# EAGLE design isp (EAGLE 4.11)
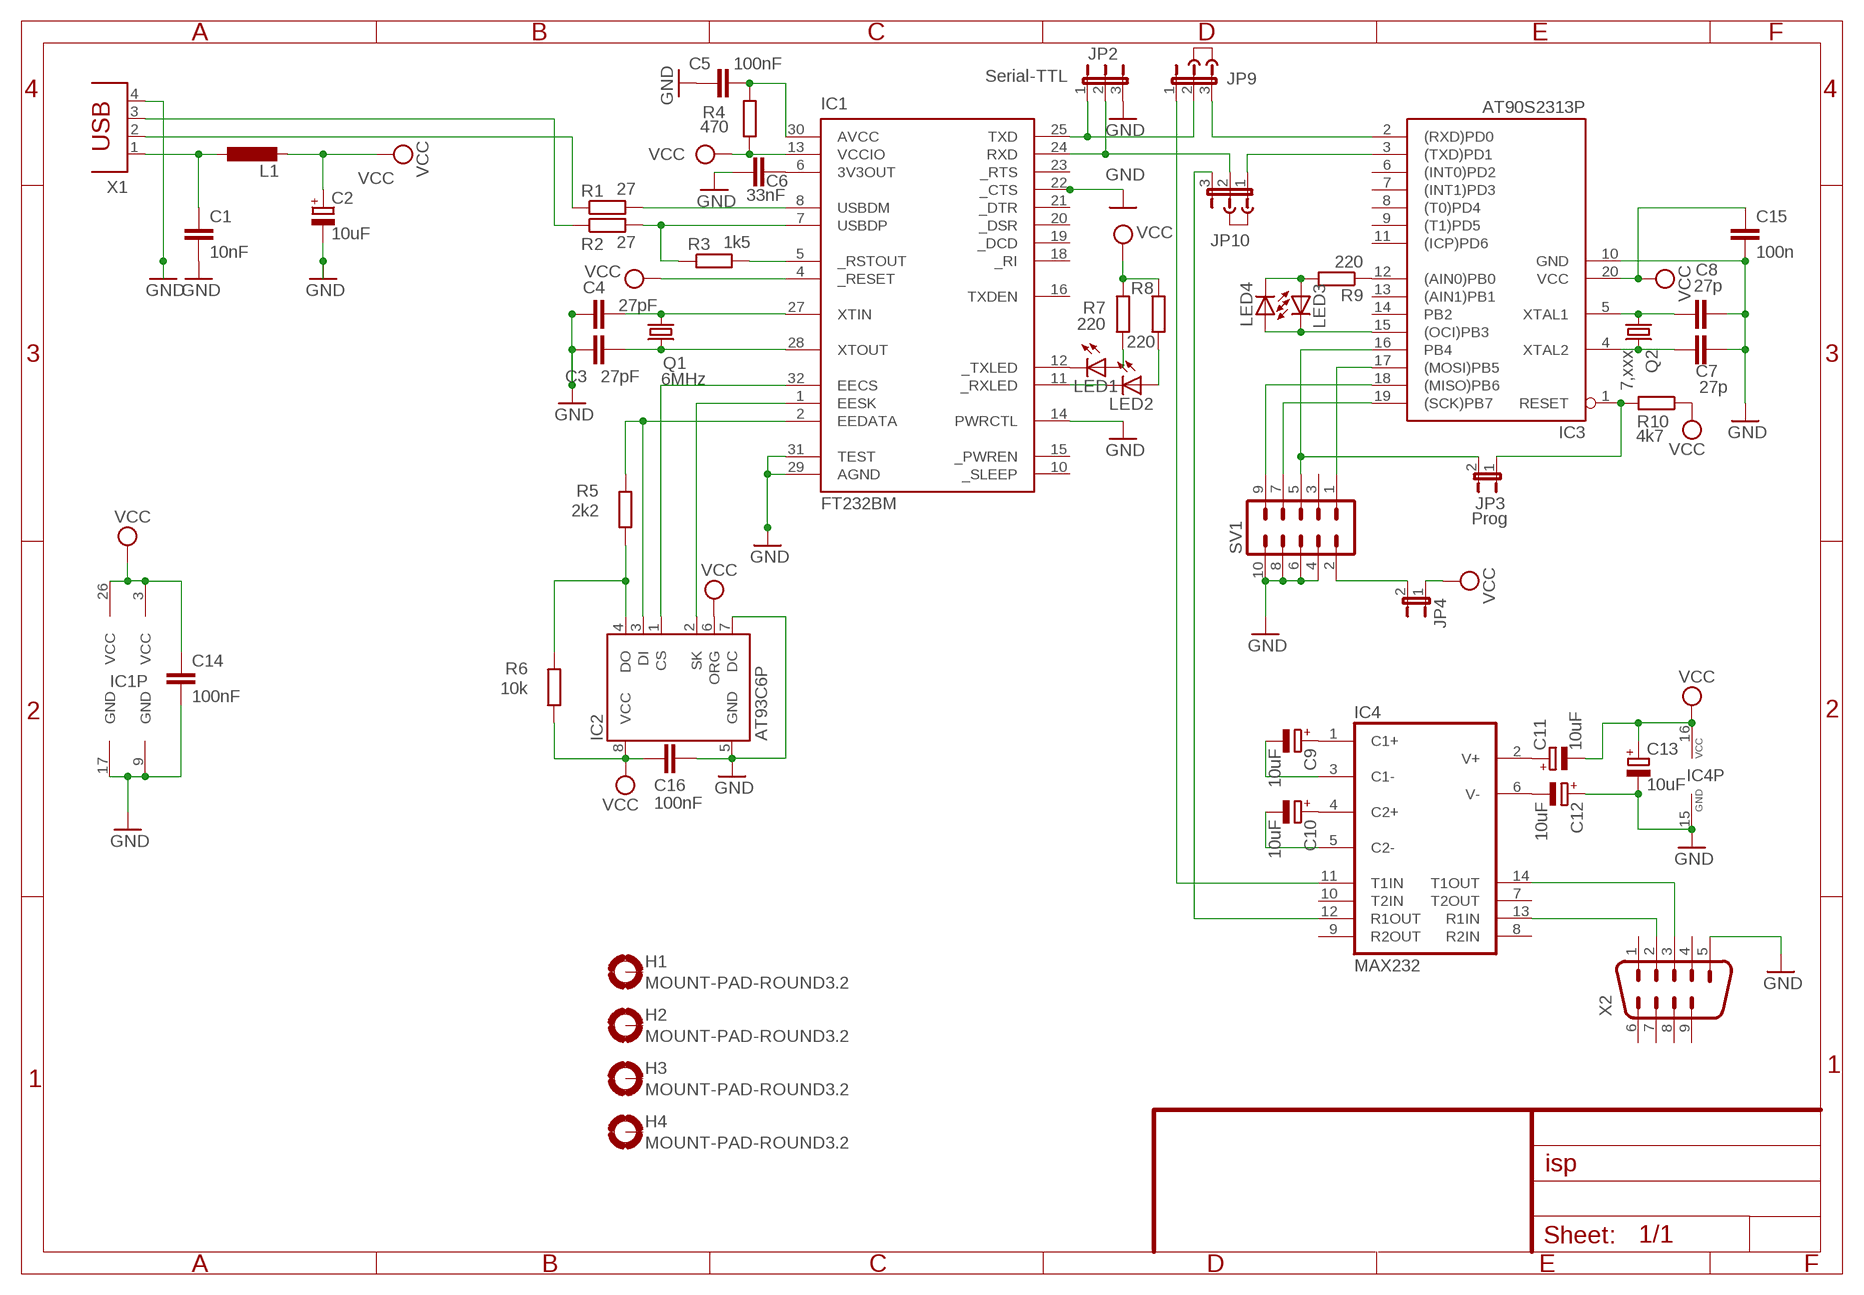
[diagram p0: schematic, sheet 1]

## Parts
C1  10nF  C-EU050-024X044  [C050-024X044]
C2  10uF  CPOL-EUE5-8.5  [E5-8,5]
C3  27pF  C-EU025-024X044  [C025-024X044]
C4  27pF  C-EU025-024X044  [C025-024X044]
C5  100nF  C-EU025-024X044  [C025-024X044]
C6  33nF  C-EU050-024X044  [C050-024X044]
C7  27p  C-EU025-024X044  [C025-024X044]
C8  27p  C-EU025-024X044  [C025-024X044]
C9  10uF  CPOL-EUE2.5-7  [E2,5-7]
C10  10uF  CPOL-EUE2.5-7  [E2,5-7]
C11  10uF  CPOL-EUE2.5-7  [E2,5-7]
C12  10uF  CPOL-EUE2.5-7  [E2,5-7]
C13  10uF  CPOL-EUE2.5-7  [E2,5-7]
C14  100nF  C-EU050-024X044  [C050-024X044]
C15  100n  C-EU050-024X044  [C050-024X044]
C16  100nF  C-EU050-024X044  [C050-024X044]
H1  MOUNT-PAD-ROUND3.2  [3,2-PAD]
H2  MOUNT-PAD-ROUND3.2  [3,2-PAD]
H3  MOUNT-PAD-ROUND3.2  [3,2-PAD]
H4  MOUNT-PAD-ROUND3.2  [3,2-PAD]
IC1  FT232BM  [LQFP32]
IC2  AT93C6P  [DIL08]
IC3  AT90S2313P  [DIL20]
IC4  MAX232  [DIL16]
J1  JUMPER  [JUMP]
J2  JUMPER  [JUMP]
JP2  Serial-TTL  JP2E  [JP2]
JP3  Prog  JP1E  [JP1]
JP4  JP1E  [JP1]
JP9  JP2E  [JP2]
JP10  JP2E  [JP2]
L1  L-EU0207/10  [0207/10]
LED1  LED3MM  [LED3MM]
LED2  LED3MM  [LED3MM]
LED3  LED3MM  [LED3MM]
LED4  LED3MM  [LED3MM]
Q1  6MHz  CRYTALHC49U-V  [HC49U-V]
Q2  7,xxx  CRYTALHC49U-V  [HC49U-V]
R1  27  R-EU_0204/7  [0204/7]
R2  27  R-EU_0204/7  [0204/7]
R3  1k5  R-EU_0204/7  [0204/7]
R4  470  R-EU_0204/7  [0204/7]
R5  2k2  R-EU_0204/7  [0204/7]
R6  10k  R-EU_0204/7  [0204/7]
R7  220  R-EU_0204/7  [0204/7]
R8  220  R-EU_0204/7  [0204/7]
R9  220  R-EU_0204/7  [0204/7]
R10  4k7  R-EU_0204/7  [0204/7]
SV1  ML10L  [ML10L]
X1  PN61729  [PN61729]
X2  M09HP  [M09HP]

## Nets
GND: C1.2 C2.- C3.2 C4.2 C5.1 C6.2 C7.1 C8.1 C12.+ C13.- C14.2 C15.2 C16.1 IC1.9(GND) IC1.14(PWRCTL) IC1.17(GND) IC1.22(_CTS) IC1.29(AGND) IC1.31(TEST) IC2.5(GND) IC2.7(DC) IC3.10(GND) IC4.15(GND) JP2.3 SV1.4 SV1.6 SV1.8 SV1.10 X1.4 X2.5
N$1: C1.1 L1.1 X1.1
N$2: IC1.7(USBDP) R2.2 R3.1
N$3: IC1.8(USBDM) R1.2
N$4: R1.1 X1.2
N$5: R2.1 X1.3
N$6: IC1.5(_RSTOUT) R3.2
N$7: IC1.32(EECS) IC2.1(CS)
N$8: C4.1 IC1.27(XTIN) Q1.1
N$9: C3.1 IC1.28(XTOUT) Q1.2
N$10: IC1.2(EEDATA) IC2.3(DI) R5.2
N$11: C5.2 IC1.30(AVCC) R4.2
N$12: C6.1 IC1.6(3V3OUT)
N$13: IC1.1(EESK) IC2.2(SK)
N$14: IC2.4(DO) R5.1 R6.2
N$15: IC3.2((RXD)PD0) JP9.3
N$16: LED1.A R7.1
N$17: LED2.A R8.1
N$18: IC1.12(_TXLED) LED1.K(C)
N$19: IC1.11(_RXLED) LED2.K(C)
N$20: C8.2 IC3.5(XTAL1) Q2.1
N$21: C7.2 IC3.4(XTAL2) Q2.2
N$23: IC3.3((TXD)PD1) JP10.1
N$24: IC3.12((AIN0)PB0) R9.1
N$25: LED3.A LED4.K(C) R9.2
N$26: IC3.15((OCI)PB3) LED3.K(C) LED4.A
N$27: IC3.1(RESET) JP3.1 R10.2
N$28: IC3.17((MOSI)PB5) SV1.1
N$29: IC3.16(PB4) JP3.2 SV1.5
N$30: IC3.18((MISO)PB6) SV1.9
N$31: IC3.19((SCK)PB7) SV1.7
N$32: JP4.2 SV1.2
N$33: IC4.11(T1IN) JP9.1
N$34: C9.+ IC4.1(C1+)
N$35: C10.+ IC4.4(C2+)
N$36: C11.+ IC4.2(V+)
N$37: C12.- IC4.6(V-)
N$38: IC4.12(R1OUT) JP10.3
N$39: IC1.25(TXD) JP2.1 JP9.2
N$40: IC1.24(RXD) JP2.2 JP10.2
N$45: IC4.14(T1OUT) X2.3
N$46: IC4.13(R1IN) X2.2
N$47: C9.- IC4.3(C1-)
N$48: C10.- IC4.5(C2-)
VCC: C2.+ C11.- C13.+ C14.1 C15.1 C16.2 IC1.3(VCC) IC1.4(_RESET) IC1.13(VCCIO) IC1.26(VCC) IC2.6(ORG) IC2.8(VCC) IC3.20(VCC) IC4.16(VCC) JP4.1 L1.2 R4.1 R6.1 R7.2 R8.2 R10.1
Unconnected: H1.B3,2(MOUNT) H2.B3,2(MOUNT) H3.B3,2(MOUNT) H4.B3,2(MOUNT) IC1.10(_SLEEP) IC1.15(_PWREN) IC1.16(TXDEN) IC1.18(_RI) IC1.19(_DCD) IC1.20(_DSR) IC1.21(_DTR) IC1.23(_RTS) IC3.6((INT0)PD2) IC3.7((INT1)PD3) IC3.8((T0)PD4) IC3.9((T1)PD5) IC3.11((ICP)PD6) IC3.13((AIN1)PB1) IC3.14(PB2) IC4.7(T2OUT) IC4.8(R2IN) IC4.9(R2OUT) IC4.10(T2IN) SV1.3 X2.1 X2.4 X2.6 X2.7 X2.8 X2.9

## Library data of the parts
C1 C3-C8 C14-C16 = rcl:C-EU: CAPACITOR, European symbol
C2 C9-C13 = rcl:CPOL-EU: POLARIZED CAPACITOR, European symbol
H1-H4 = holes:MOUNT-PAD-ROUND: MOUNTING PAD, round
IC1 = ftdi3:FT232BM: USB UART 2nd Generation USB UART (USB <-> Serial)
IC2 = atmel:AT93C*6: 3-wire serial EEPROM
IC3 = atmel:AT90S2313: MICROCONTROLLER 2 Kbytes FLASH 128 bytes SRAM 128 bytes EEPROM UART
IC4 = maxim:MAX232: RS232 TRANSEIVER
J1 J2 = jumper:JUMPER: JUMPER header
JP2 JP9 JP10 = jumper:JP2E: JUMPER
JP3 JP4 = jumper:JP1E: JUMPER
L1 = rcl:L-EU: INDUCTOR, European symbol
LED1-LED4 = led:LED: LED
Q1 Q2 = crystal:CRYTAL: CRYSTAL
R1-R10 = rcl:R-EU_: RESISTOR, European symbol
SV1 = con-harting-ml:ML10: HARTING
X1 = con-berg:PN61729: BERG USB connector
X2 = con-subd:M09: SUB-D

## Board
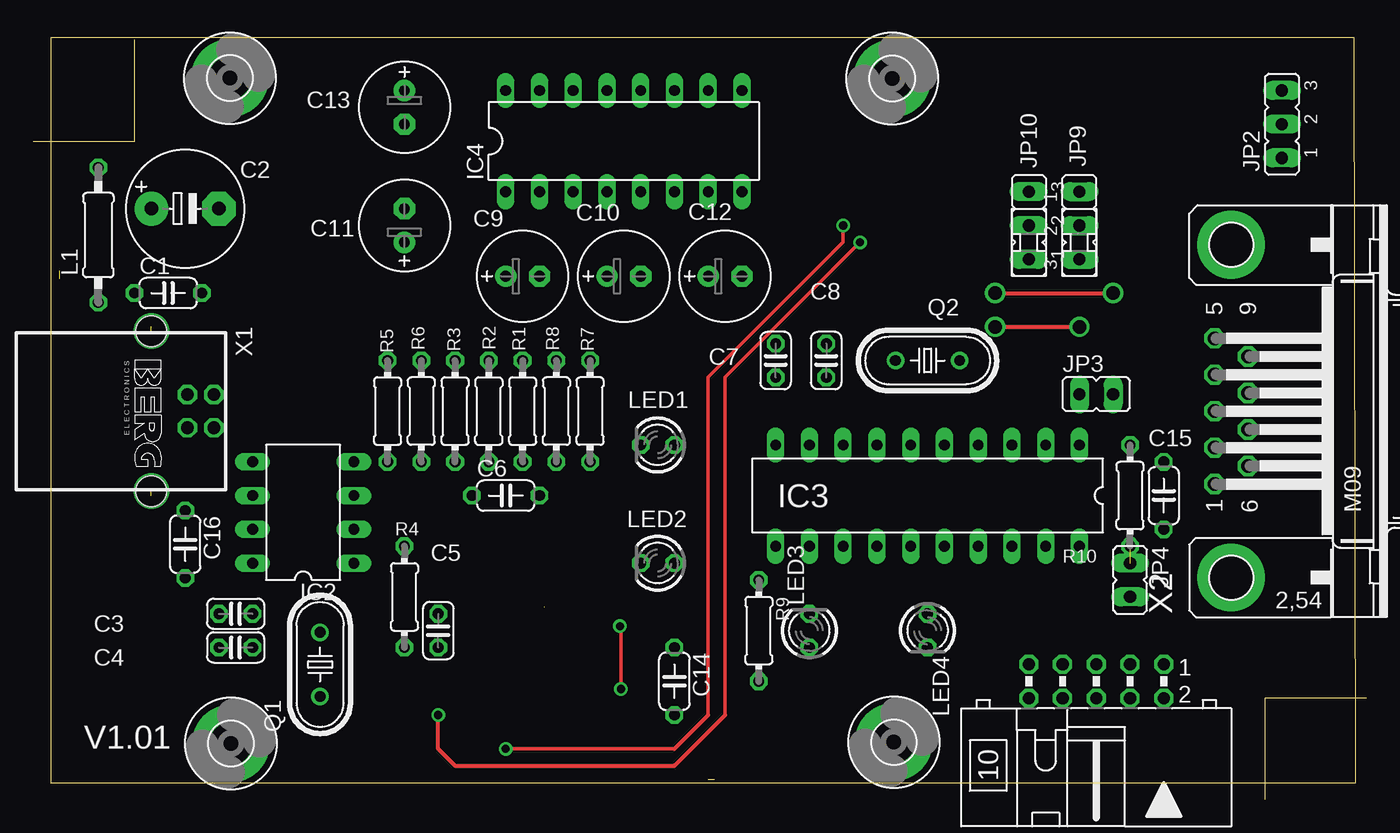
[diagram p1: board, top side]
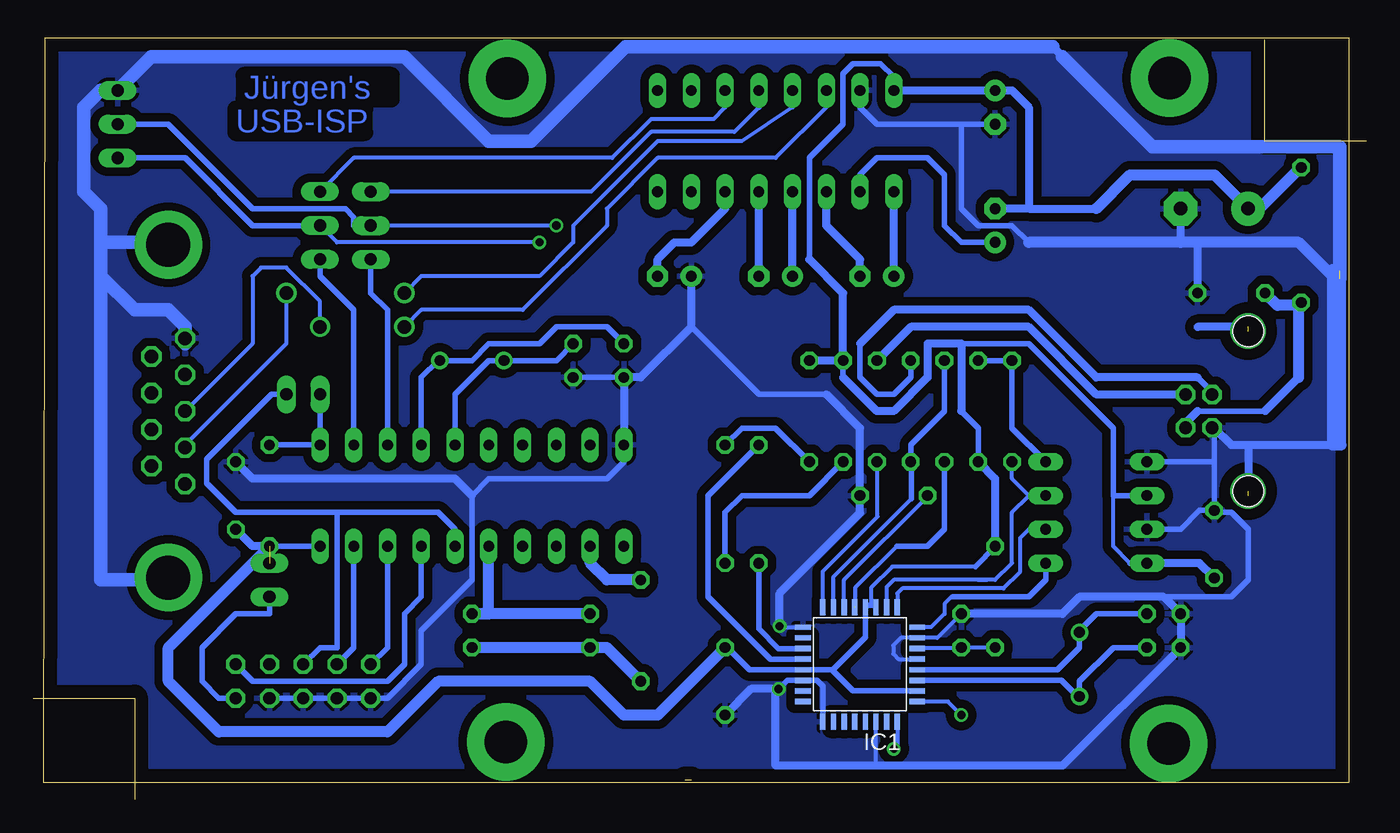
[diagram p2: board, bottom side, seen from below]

Size 100.33 x 57.31 mm. Coordinates in mm from the lower left corner, seen from the top.
Outline: 0,49.53 7.62,49.53 7.62,57.15
Outline: 100.33,7.62 92.71,7.62 92.71,0
Outline: 51.27,1.47 50.8,1.47
Outline: 1.3,1.24 99.53,1.24 99.43,57.31 1.3,57.31 1.3,1.24
Copper layers (1*16): Top 0.035mm / dielectric 1.5mm / Bottom 0.035mm
Design rules "default": minimum track width 10mil, minimum drill 24mil, track to track 25mil, track to pad 25mil, pad to pad 8mil, via to via 8mil, smd to smd 8mil, copper to edge 40mil, drill to drill 8mil, minimum pad ring 10mil, minimum via ring 8mil, stop-mask expansion 4mil, vias tented up to drill 0mil, thermal gap 10mil

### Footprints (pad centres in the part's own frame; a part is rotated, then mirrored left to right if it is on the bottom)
C050-024X044 = drill 0.813 octagon: 1 -2.54,0; 2 2.54,0
E5-8,5 = drill 1.016 pad 2.54 round: + -2.54,0 | drill 1.016 pad 2.54 octagon: - 2.54,0
C025-024X044 = drill 0.813 octagon: 1 -1.27,0; 2 1.27,0
E2,5-7 = drill 0.813 pad 1.6 round: + -1.27,0 | drill 0.813 pad 1.6 octagon: - 1.27,0
3,2-PAD = drill 3.2 pad 5.842 round: B3,2 0,0
LQFP32 = smd 0.4 x 1.2: 1 -2.8,-4.3; 2 -2,-4.3; 3 -1.2,-4.3; 4 -0.4,-4.3; 5 0.4,-4.3; 6 1.2,-4.3; 7 2,-4.3; 8 2.8,-4.3; 17 2.8,4.3; 18 2,4.3; 19 1.2,4.3; 20 0.4,4.3; 21 -0.4,4.3; 22 -1.2,4.3; 23 -2,4.3; 24 -2.8,4.3 | smd 1.2 x 0.4: 9 4.3,-2.8; 10 4.3,-2; 11 4.3,-1.2; 12 4.3,-0.4; 13 4.3,0.4; 14 4.3,1.2; 15 4.3,2; 16 4.3,2.8; 25 -4.3,2.8; 26 -4.3,2; 27 -4.3,1.2; 28 -4.3,0.4; 29 -4.3,-0.4; 30 -4.3,-1.2; 31 -4.3,-2; 32 -4.3,-2.8
DIL08 = drill 0.813 long: 1 -3.81,-3.81; 2 -1.27,-3.81; 3 1.27,-3.81; 4 3.81,-3.81; 5 3.81,3.81; 6 1.27,3.81; 7 -1.27,3.81; 8 -3.81,3.81
DIL20 = drill 0.813 long: 1 -11.43,-3.81; 2 -8.89,-3.81; 3 -6.35,-3.81; 4 -3.81,-3.81; 5 -1.27,-3.81; 6 1.27,-3.81; 7 3.81,-3.81; 8 6.35,-3.81; 9 8.89,-3.81; 10 11.43,-3.81; 11 11.43,3.81; 12 8.89,3.81; 13 6.35,3.81; 14 3.81,3.81; 15 1.27,3.81; 16 -1.27,3.81; 17 -3.81,3.81; 18 -6.35,3.81; 19 -8.89,3.81; 20 -11.43,3.81
DIL16 = drill 0.813 long: 1 -8.89,-3.81; 2 -6.35,-3.81; 3 -3.81,-3.81; 4 -1.27,-3.81; 5 1.27,-3.81; 6 3.81,-3.81; 7 6.35,-3.81; 8 8.89,-3.81; 9 8.89,3.81; 10 6.35,3.81; 11 3.81,3.81; 12 1.27,3.81; 13 -1.27,3.81; 14 -3.81,3.81; 15 -6.35,3.81; 16 -8.89,3.81
JP2 = drill 0.914 long: 1 -2.54,0; 2 0,0; 3 2.54,0
JP1 = drill 0.914 long: 1 0,-1.27; 2 0,1.27
0207/10 = drill 0.813 octagon: 1 -5.08,0; 2 5.08,0
LED3MM = drill 0.813 octagon: A -1.27,0; K 1.27,0
HC49U-V = drill 0.813 round: 1 -2.413,0; 2 2.413,0
0204/7 = drill 0.813 octagon: 1 -3.81,0; 2 3.81,0
ML10L = drill 0.914 octagon: 1 -5.08,-1.27; 2 -5.08,1.27; 3 -2.54,-1.27; 4 -2.54,1.27; 5 0,-1.27; 6 0,1.27; 7 2.54,-1.27; 8 2.54,1.27; 9 5.08,-1.27; 10 5.08,1.27
PN61729 = drill 0.95 octagon: 1 1.25,4.71; 2 -1.25,4.71; 3 -1.25,2.71; 4 1.25,2.71 | hole 2.3: -6.02,0; 6.02,0
M09HP = drill 1.016 octagon: 1 -5.486,1.27; 2 -2.743,1.27; 3 0,1.27; 4 2.743,1.27; 5 5.486,1.27; 6 -4.115,-1.27; 7 -1.372,-1.27; 8 1.372,-1.27; 9 4.115,-1.27 | drill 3.302 pad 5.08 round: G1 -12.522,0; G2 12.522,0

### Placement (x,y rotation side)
C1  10.16,38.1 0 top
C2  11.43,44.45 0 top
C3  15.24,13.97 180 top
C4  15.24,11.43 180 top
C5  30.48,12.7 270 top
C6  35.56,22.86 0 top
C7  55.88,33.02 90 top
C8  59.69,33.02 90 top
C9  36.83,39.37 0 top
C10  44.45,39.37 0 top
C11  27.94,43.18 90 top
C12  52.07,39.37 0 top
C13  27.94,52.07 270 top
C14  48.26,8.89 270 top
C15  85.09,22.86 90 top
C16  11.44,19.2 270 top
H1  14.8,54.27 0 top
H2  64.65,54.24 0 top
H3  64.77,4.31 0 top
H4  14.88,4.21 0 top
IC1  38.1,10.16 180 bottom
IC2  20.32,21.59 90 top
IC3  67.31,22.86 180 top
IC4  44.45,49.53 0 top
J1  74.93,41.91 0 top
J2  78.74,41.91 0 top
JP2  93.98,50.8 90 top
JP3  80.01,30.48 270 top
JP4  82.55,16.51 180 top
JP9  78.74,43.18 270 top
JP10  74.93,43.18 90 top
L1  4.9,42.46 90 top
LED1  46.99,26.67 180 top
LED2  46.99,17.78 180 top
LED3  58.42,12.7 90 top
LED4  67.31,12.7 270 top
Q1  21.59,10.16 90 top
Q2  67.31,33.02 0 top
R1  36.83,29.21 270 top
R2  34.29,29.21 270 top
R3  31.75,29.21 270 top
R4  27.94,15.24 270 top
R5  26.67,29.21 270 top
R6  29.21,29.21 90 top
R7  41.91,29.21 90 top
R8  39.37,29.21 90 top
R9  54.61,12.7 270 top
R10  82.55,22.86 90 top
SV1  80.01,8.89 180 top
X1  8.89,29.21 270 top
X2  90.17,29.21 90 top

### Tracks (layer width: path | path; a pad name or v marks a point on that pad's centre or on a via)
GND  (via drill 0.61, 1.78)  (2 unrouted)
  Top 0.254: v44.23,8.31 44.23,12.95
  Top 0.406: 44.23,12.95 v44.15,13.03
  Bottom 0.305: IC1.31 32.29,12.16 C5.1 | IC1.29 35.2,10.56 35.59,10.95 35.59,11.59 35.03,12.15 33.91,12.15 | v44.15,13.03 44.15,12.95 44.14,12.96 IC1.9 | IC1.22 36.9,2.61 36.83,2.54
  Bottom 0.406: IC4.15 38.1,52.07 36.83,50.8 30.48,50.8 | 30.48,50.8 C13.- | 30.48,50.8 30.48,44.45 29.21,43.18 26.67,43.18 25.4,41.91 | SV1.4 SV1.6 SV1.8 SV1.10 73.66,7.62 71.12,10.16 71.12,12.7 67.31,16.51 67.31,22.86 66.04,24.13 57.15,24.13 55.88,25.4 IC3.10 | 40.64,30.48 45.72,30.48 50.8,35.56 | 33.91,12.15 33.9,12.16 IC1.31 | IC1.17 40.9,8.5 41.35,8.95 42.31,8.95 42.32,8.96 IC1.14 43.58,8.96 v44.23,8.31 | C16.1 12.55,21.74 13.97,20.32 IC2.7 | 11.45,27.96 X1.4 | 11.44,25.4 11.44,27.93 11.43,27.94 | C16.1 11.44,25.4 | 11.44,25.4 11.43,25.4 | 11.44,25.4 IC2.5 | 15.24,15.24 10.16,15.24 8.89,16.51 8.89,20.32 10.16,21.59 11.43,21.59 11.44,21.6 C16.1 | C7.1 C8.1
  Bottom 0.61: C12.+ 50.8,35.56 54.61,31.75 C7.1 IC3.10 | 40.64,30.48 38.1,27.94 C6.2 38.1,21.56 44.15,15.51 v44.15,13.03 | C5.1 22.86,13.97 21.59,15.24 15.24,15.24 C3.2 C4.2 22.86,2.54 36.83,2.54 44.45,2.54 44.45,8.25 44.31,8.39 v44.23,8.31 46.3,8.31 C14.2 | 22.86,55.88 22.86,55.9 23.59,56.63 | C15.2 83.82,24.13 68.58,24.13 67.31,22.86 | 8.89,26.67 10.16,26.67 11.43,27.94 11.45,27.96 | 8.89,26.67 2.54,26.67 | 12.7,41.91 C1.2 | 13.97,41.91 C2.- | 8.89,26.67 8.89,22.86
  Bottom 0.813: 2.54,39.37 2.54,39.86 2.01,39.86 2.01,39.77 1.91,39.77 1.91,26.67 2.54,26.67 2.54,39.37 | 25.4,41.91 13.97,41.91 12.7,41.91 5.08,41.91 2.54,39.37
  Bottom 1.016: 95.25,41.91 95.25,44.45 96.52,45.72 96.52,52.07 95.25,53.34 JP2.3 91.44,55.88 72.39,55.88 66.04,49.53 62.85,49.53 55.75,56.63 23.59,56.63 | 95.25,41.91 95.25,39.37 | 95.25,39.37 92.71,36.83 90.17,36.83 88.9,35.56 X2.5 88.9,34.29 | 1.99,39.19 1.99,49.11 16.09,49.11 22.86,55.88 | 95.25,41.91 90.17,41.91 | 95.25,39.37 95.25,16.51 90.17,16.51
  other vias: 8.89,23.19
  pour Bottom: 7.62,57.15 99.06,57.15 99.06,7.62 92.71,7.62 92.71,1.27 1.27,1.27 1.27,49.53 2.54,49.53 7.62,49.53
N$1
  Bottom 0.305: 13.97,27.94 13.95,27.96 X1.1
  Bottom 0.406: 7.62,29.21 12.7,29.21
  Bottom 0.61: 7.62,29.21 5.08,31.75 | 12.7,29.21 13.95,27.96
  Bottom 0.813: 4.87,37.38 4.84,37.41 | 4.87,37.38 L1.1 | 5.08,31.75 5.08,37.17 | 5.08,37.17 4.87,37.38 | 5.08,37.17 6.69,37.17 C1.1
N$2
  Bottom 0.305: IC1.7 40.1,16.76 34.23,22.63
  Bottom 0.406: 34.23,22.63 34.23,25.43 34.26,25.43 R2.2 34.29,26.67 31.75,29.21 R3.1
N$3
  Bottom 0.305: IC1.8 40.9,17.16 36.79,21.27 36.79,25.35 R1.2
N$4
  Bottom 0.61: X1.2 20.3,30.46 25.4,35.56 34.29,35.56 R1.1
N$5
  Bottom 0.305: 11.43,30.48 11.45,30.46 X1.3
  Bottom 0.406: 38.1,34.29 38.1,31.75 36.83,30.48 35.56,30.48 34.29,31.75 R2.1 | 11.43,30.48 12.7,31.75
  Bottom 0.61: 38.1,34.29 35.56,36.83 25.4,36.83 20.32,31.75 12.7,31.75
N$6  (1 unrouted)
  Bottom 0.305: 38.47,14.49 38.47,15.91 35.33,19.05
  Bottom 0.406: 35.33,19.05 33.02,19.05 31.75,20.32 R3.2
N$7
  Bottom 0.305: IC1.32 32.76,12.96 31.75,13.97 31.75,14.71 31.19,15.27 31.16,15.24 31.11,15.24
  Bottom 0.406: 31.11,15.24 25.4,15.24 24.13,16.51 IC2.1
N$8
  Bottom 0.406: IC1.27 22.93,8.96 21.59,7.62 Q1.1 21.59,8.89 19.05,11.43 C4.1
N$9
  Bottom 0.406: IC1.28 23.26,9.76 21.59,11.43 Q1.2 21.59,12.7 20.32,13.97 C3.1
N$10
  Bottom 0.305: IC1.2 36.1,15.97 35.56,16.51 29.21,16.51 | 29.21,16.51 28.57,16.51 | R5.2 26.67,24.13 25.4,22.86 | 25.4,22.86 IC2.3 | 25.4,22.86 26.67,21.59 26.67,17.78 27.94,16.51 29.21,16.51
N$11
  Bottom 0.305: R4.2 C5.2 | 30.55,11.36 IC1.30
  Bottom 0.406: C5.2 30.55,11.36
N$12
  Bottom 0.305: 32.96,22.86 32.95,22.87 | 32.96,22.86 C6.1 | IC1.6 39.3,16.52 32.96,22.86
N$13
  Bottom 0.305: IC1.1 35.3,15.5 34.93,15.88 27.3,15.88 26.04,17.14 26.04,19.68 25.4,20.32 IC2.2
N$14
  Bottom 0.406: R6.2 R5.1 26.67,27.94 IC2.4
N$15
  Bottom 0.406: JP9.3 78.74,39.37 76.2,36.83 IC3.2
N$16
  Bottom 0.406: R7.1 44.45,27.94 46.99,27.94 LED1.A
N$17
  Bottom 0.406: LED2.A 48.26,21.59 46.99,22.86 41.91,22.86 R8.1
N$18
  Bottom 0.406: LED1.K 49.53,22.86 49.53,15.24 44.84,10.55 IC1.12
N$19
  Bottom 0.406: LED2.K 45.72,12.84 44.23,11.35 IC1.11
N$20
  Bottom 0.406: IC3.5 68.58,30.48 66.04,33.02 Q2.1 | Q2.1 64.77,33.02 | Q2.1 60.96,33.02 C8.2
N$21
  Bottom 0.406: IC3.4 71.12,31.75 69.85,33.02 Q2.2 67.31,33.02 66.04,34.29 62.23,34.29 60.96,35.56 57.15,35.56 C7.2
N$22  (via drill 1.78)  (1 unrouted)
  Bottom 0.61: 8.89,35.56 12.7,35.56
  other vias: 8.88,35.23
N$23
  Bottom 0.406: JP10.1 74.93,38.1 73.66,36.83 IC3.3
N$24
  Bottom 0.813: R9.1 57.15,16.51 58.42,17.78 IC3.12
N$25
  Bottom 0.813: LED4.K LED3.A 57.15,11.43 R9.2
N$26
  Bottom 0.813: IC3.15 66.04,13.97 LED4.A LED3.K
N$27
  Bottom 0.406: R10.2 IC3.1 JP3.1
N$28
  Bottom 0.406: IC3.17 71.12,15.24 72.39,13.97 72.39,10.16 73.66,8.89 83.82,8.89 SV1.1
N$29
  Bottom 0.406: 77.47,21.59 69.85,21.59 68.58,20.32 IC3.16 | 77.47,21.59 77.47,11.43 78.74,11.43 SV1.5 | 87.27,24.71 87.27,23.77 85.09,21.59 77.47,21.59 | 87.27,24.71 87.27,24.79 | JP3.2 82.38,30.48 87.27,25.59 87.27,24.71
N$30
  Bottom 0.406: IC3.18 73.66,11.43 SV1.9
N$31
  Bottom 0.406: IC3.19 76.2,11.43 SV1.7
N$32
  Bottom 0.406: JP4.2 82.55,13.97 85.09,13.97 87.63,11.43 87.63,8.89 86.36,7.62 SV1.2
N$33
  Bottom 0.305: IC4.11 48.26,52.07 49.14,51.19 53.83,51.19 56.76,48.26 76.2,48.26 JP9.1
N$34
  Bottom 0.61: C9.+ IC4.1
N$35
  Bottom 0.61: C10.+ IC4.4
N$36
  Bottom 0.406: IC4.2 38.1,46.99 36.83,48.26 33.02,48.26 31.75,46.99 31.75,43.18 30.48,41.91 C11.+
N$37
  Bottom 0.61: C12.- 53.34,40.64 52.07,41.91 50.8,41.91 48.26,44.45 IC4.6
N$38
  Bottom 0.305: 45.72,52.07 47.56,50.23 53.83,50.23 58.34,45.72 JP10.3
  Bottom 0.406: IC4.12 45.72,52.07
N$39  (via drill 0.61)
  Top 0.254: v62.23,41.91 52.07,31.75 52.07,6.35
  Top 0.305: 52.07,6.35 48.26,2.54 31.75,2.54 30.48,3.81 v30.48,6.35
  Bottom 0.305: JP9.2 77.47,41.91 v62.23,41.91 | IC1.25 33.83,7.35 | IC1.25 | v30.48,6.35 31.48,7.35 IC1.25
  Bottom 0.406: JP9.2 83.82,43.18 88.9,48.26 JP2.1
N$40  (via drill 0.61)
  Top 0.254: v60.96,43.18 60.96,41.91 50.8,31.75 50.8,6.35 | v35.56,3.81 48.26,3.81
  Top 0.305: 48.26,3.81 50.8,6.35
  Bottom 0.305: v60.96,43.18 JP10.2 | IC1.24 35.27,5.83 35.27,4.1 v35.56,3.81
  Bottom 0.406: JP10.2 76.2,43.18 76.2,43.82 76.83,44.45 83.82,44.45 90.17,50.8 JP2.2
N$45  (via drill 1.02 pad 0.61)
  Top 0.305: v72.39,35.56 v78.74,35.56
  Bottom 0.305: IC4.14 40.64,52.07 44.45,48.26 53.34,48.26 57.15,44.45 57.15,43.18 63.5,36.83 71.12,36.83 v72.39,35.56 | v78.74,35.56 78.74,37.47 81.28,40.01 83.19,40.01 83.82,39.37 83.82,34.29 X2.3
N$46  (via drill 1.02 pad 0.61)
  Top 0.305: v72.39,38.1 v81.28,38.1
  Bottom 0.305: IC4.13 43.18,52.07 46.99,49.53 53.34,49.53 59.69,43.18 59.69,41.91 62.23,39.37 71.12,39.37 v72.39,38.1 | X2.2 88.9,26.67 81.28,34.29 v81.28,38.1
N$47
  Bottom 0.61: C9.- 38.1,40.64 40.64,43.18 IC4.3
N$48
  Bottom 0.61: C10.- IC4.5
VCC  (1 unrouted)
  Bottom 0.305: IC1.3 36.9,14.6 36.87,14.63 37.27,14.63 37.27,15.91 35.67,17.51 29.43,17.51 | 19.05,22.86 19.05,19.05 17.78,17.78
  Bottom 0.406: 41.91,40.64 41.91,48.26 39.37,50.8 39.37,54.61 38.63,55.35 36.55,55.35 35.56,54.36 IC4.16 | R10.1 IC3.20 | 39.37,31.75 R8.2 | IC1.3 37.05,14.61 37.55,14.61 IC1.4 37.7,12.2 40.19,9.71 | IC1.13 42.07,9.75 | IC1.26 38.64,8.16 40.19,9.71 | 40.19,9.71 40.23,9.75 IC1.13 | IC1.13 | R4.1 27.91,19.03 29.43,17.51 | C14.1 48.21,11.43 48.16,11.48 46.43,9.75 IC1.13 | IC2.8 17.78,17.78 | R6.1 29.21,27.94 30.48,29.21 | IC2.6 19.05,22.86 19.05,27.94 25.4,34.29 30.48,34.29
  Bottom 0.61: R6.1 27.94,24.13 R4.1 | R7.2 R8.2 39.37,38.1 41.91,40.64 | 25.4,44.45 20.32,44.45 | 25.4,44.45 C11.- | IC4.16 C13.+ 26.67,53.34 25.4,52.07 25.4,44.45 | 39.37,31.75 36.83,29.21 35.56,29.21 33.02,31.75 33.02,34.29 30.48,34.29 30.48,29.21 | C15.1 83.82,19.05 R10.1 | C16.2 12.56,17.78 IC2.8
  Bottom 0.813: L1.2 4.9,47.6 4.91,47.61 8.07,44.45 C2.+ 11.43,46.99 17.78,46.99 20.32,44.45 | C14.1 53.34,6.35 55.88,6.35 58.42,8.89 69.85,8.89 73.66,5.08 86.36,5.08 90.17,8.89 90.17,11.43 R10.1

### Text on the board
Bottom: Jürgen's | USB-ISP
tNames: V1.01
